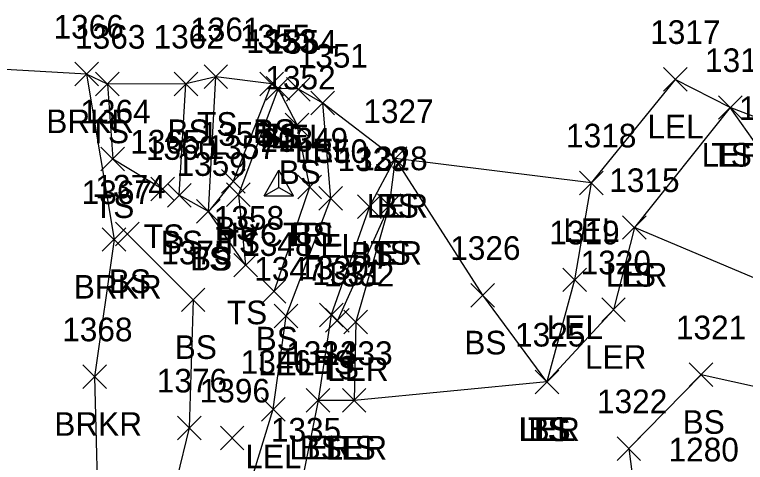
# Model space of a CAD drawing. Extents: x 1505684 to 1510253, y 730355 to 731397.
# Drawn here: x 1510141.5 to 1510203.3, y 730957.3 to 730995.2 of the extents above; entities that cross this region are included whole.
import ezdxf

# ---------------------------------------------------------------- set-up
doc = ezdxf.new("R2010")
doc.units = 0
for name, color, linetype in [('C_A', 7, 'Continuous'), ('C_I', 7, 'Continuous'), ('CPSM', 7, 'Continuous'), ('L_A', 7, 'Continuous'), ('L_I', 7, 'Continuous'), ('L_TIC', 7, 'Continuous'), ('LARO', 7, 'Continuous'), ('LAWE', 7, 'Continuous'), ('LELB', 7, 'Continuous'), ('LSOGP', 7, 'Continuous')]:
    doc.layers.add(name, color=color, linetype=linetype)

msp = doc.modelspace()

# ---------------------------------------------------------------- linework, layer by layer
at = {"layer": 'CPSM'}
for p, q in [((1510162.575, 730979.849), (1510163.825, 730982.014)), ((1510165.075, 730979.849), (1510163.825, 730982.014)), ((1510163.825, 730980.57), (1510163.825, 730982.014)), ((1510162.575, 730979.849), (1510163.825, 730980.57)), ((1510163.825, 730980.57), (1510163.825, 730980.57)), ((1510163.825, 730980.57), (1510165.075, 730979.849)), ((1510162.575, 730979.849), (1510165.075, 730979.849))]:
    msp.add_line(p, q, dxfattribs=at)
at = {"layer": 'L_TIC'}
for points in [[(1510146.562, 730989.156), (1510148.562, 730991.156)], [(1510148.562, 730989.156), (1510146.562, 730991.156)], [(1510157.499, 730988.933), (1510159.499, 730990.933)], [(1510159.499, 730988.933), (1510157.499, 730990.933)], [(1510148.331, 730988.302), (1510150.331, 730990.302)], [(1510150.331, 730988.302), (1510148.331, 730990.302)], [(1510154.968, 730988.315), (1510156.968, 730990.315)], [(1510156.968, 730988.315), (1510154.968, 730990.315)], [(1510162.22, 730988.325), (1510164.22, 730990.325)], [(1510164.22, 730988.325), (1510162.22, 730990.325)], [(1510196.37, 730988.705), (1510198.37, 730990.705)], [(1510198.37, 730988.705), (1510196.37, 730990.705)], [(1510162.768, 730987.944), (1510164.768, 730989.944)], [(1510164.768, 730987.944), (1510162.768, 730989.944)], [(1510162.768, 730987.944), (1510164.768, 730989.944)], [(1510164.768, 730987.944), (1510162.768, 730989.944)], [(1510164.484, 730987.873), (1510166.484, 730989.873)], [(1510166.484, 730987.873), (1510164.484, 730989.873)], [(1510166.547, 730986.697), (1510168.547, 730988.697)], [(1510168.547, 730986.697), (1510166.547, 730988.697)], [(1510201.014, 730986.326), (1510203.014, 730988.326)], [(1510203.014, 730986.326), (1510201.014, 730988.326)], [(1510201.014, 730986.326), (1510203.014, 730988.326)], [(1510203.014, 730986.326), (1510201.014, 730988.326)], [(1510164.377, 730984.851), (1510166.377, 730986.851)], [(1510166.377, 730984.851), (1510164.377, 730986.851)], [(1510172.671, 730982.007), (1510174.671, 730984.007)], [(1510174.671, 730982.007), (1510172.671, 730984.007)], [(1510172.671, 730982.007), (1510174.671, 730984.007)], [(1510174.671, 730982.007), (1510172.671, 730984.007)], [(1510148.777, 730981.976), (1510150.777, 730983.976)], [(1510150.777, 730981.976), (1510148.777, 730983.976)], [(1510158.968, 730980.086), (1510160.968, 730982.086)], [(1510160.968, 730980.086), (1510158.968, 730982.086)], [(1510165.448, 730979.599), (1510167.448, 730981.599)], [(1510167.448, 730979.599), (1510165.448, 730981.599)], [(1510189.257, 730979.947), (1510191.257, 730981.947)], [(1510191.257, 730979.947), (1510189.257, 730981.947)], [(1510152.993, 730979.431), (1510154.993, 730981.431)], [(1510154.993, 730979.431), (1510152.993, 730981.431)], [(1510159.407, 730978.959), (1510161.407, 730980.959)], [(1510161.407, 730978.959), (1510159.407, 730980.959)], [(1510154.401, 730978.897), (1510156.401, 730980.897)], [(1510156.401, 730978.897), (1510154.401, 730980.897)], [(1510167.214, 730978.63), (1510169.214, 730980.63)], [(1510169.214, 730978.63), (1510167.214, 730980.63)], [(1510170.486, 730977.94), (1510172.486, 730979.94)], [(1510172.486, 730977.94), (1510170.486, 730979.94)], [(1510172.163, 730978.018), (1510174.163, 730980.018)], [(1510174.163, 730978.018), (1510172.163, 730980.018)], [(1510172.163, 730978.018), (1510174.163, 730980.018)], [(1510174.163, 730978.018), (1510172.163, 730980.018)], [(1510156.871, 730977.538), (1510158.871, 730979.538)], [(1510158.871, 730977.538), (1510156.871, 730979.538)], [(1510156.871, 730977.538), (1510158.871, 730979.538)], [(1510158.871, 730977.538), (1510156.871, 730979.538)], [(1510192.91, 730976.171), (1510194.91, 730978.171)], [(1510194.91, 730976.171), (1510192.91, 730978.171)], [(1510192.91, 730976.171), (1510194.91, 730978.171)], [(1510194.91, 730976.171), (1510192.91, 730978.171)], [(1510150.004, 730975.626), (1510152.004, 730977.626)], [(1510152.004, 730975.626), (1510150.004, 730977.626)], [(1510148.891, 730975.157), (1510150.891, 730977.157)], [(1510150.891, 730975.157), (1510148.891, 730977.157)], [(1510160.018, 730972.985), (1510162.018, 730974.985)], [(1510162.018, 730972.985), (1510160.018, 730974.985)], [(1510187.848, 730971.742), (1510189.848, 730973.742)], [(1510189.848, 730971.742), (1510187.848, 730973.742)], [(1510162.425, 730970.767), (1510164.425, 730972.767)], [(1510164.425, 730970.767), (1510162.425, 730972.767)], [(1510180.076, 730970.432), (1510182.076, 730972.432)], [(1510182.076, 730970.432), (1510180.076, 730972.432)], [(1510155.58, 730970.051), (1510157.58, 730972.051)], [(1510157.58, 730970.051), (1510155.58, 730972.051)], [(1510191.142, 730969.212), (1510193.142, 730971.212)], [(1510193.142, 730969.212), (1510191.142, 730971.212)], [(1510163.438, 730968.672), (1510165.438, 730970.672)], [(1510165.438, 730968.672), (1510163.438, 730970.672)], [(1510167.262, 730968.776), (1510169.262, 730970.776)], [(1510169.262, 730968.776), (1510167.262, 730970.776)], [(1510167.782, 730968.304), (1510169.782, 730970.304)], [(1510169.782, 730968.304), (1510167.782, 730970.304)], [(1510169.338, 730968.187), (1510171.338, 730970.187)], [(1510171.338, 730968.187), (1510169.338, 730970.187)], [(1510147.239, 730963.543), (1510149.239, 730965.543)], [(1510149.239, 730963.543), (1510147.239, 730965.543)], [(1510198.546, 730963.713), (1510200.546, 730965.713)], [(1510200.546, 730963.713), (1510198.546, 730965.713)], [(1510185.509, 730963.098), (1510187.509, 730965.098)], [(1510187.509, 730963.098), (1510185.509, 730965.098)], [(1510185.509, 730963.098), (1510187.509, 730965.098)], [(1510187.509, 730963.098), (1510185.509, 730965.098)], [(1510185.509, 730963.098), (1510187.509, 730965.098)], [(1510187.509, 730963.098), (1510185.509, 730965.098)], [(1510185.509, 730963.098), (1510187.509, 730965.098)], [(1510187.509, 730963.098), (1510185.509, 730965.098)], [(1510166.147, 730961.543), (1510168.147, 730963.543)], [(1510168.147, 730961.543), (1510166.147, 730963.543)], [(1510166.147, 730961.543), (1510168.147, 730963.543)], [(1510168.147, 730961.543), (1510166.147, 730963.543)], [(1510169.201, 730961.539), (1510171.201, 730963.539)], [(1510171.201, 730961.539), (1510169.201, 730963.539)], [(1510169.201, 730961.539), (1510171.201, 730963.539)], [(1510171.201, 730961.539), (1510169.201, 730963.539)], [(1510162.353, 730960.789), (1510164.353, 730962.789)], [(1510164.353, 730960.789), (1510162.353, 730962.789)], [(1510155.251, 730959.212), (1510157.251, 730961.212)], [(1510157.251, 730959.212), (1510155.251, 730961.212)], [(1510158.881, 730958.364), (1510160.881, 730960.364)], [(1510160.881, 730958.364), (1510158.881, 730960.364)], [(1510192.439, 730957.459), (1510194.439, 730959.459)], [(1510194.439, 730957.459), (1510192.439, 730959.459)]]:
    msp.add_lwpolyline(points, dxfattribs=at)
at = {"layer": 'LARO'}
for points in [[(1510197.37, 730989.705), (1510190.257, 730980.947), (1510188.848, 730972.742), (1510186.509, 730964.098)], [(1510161.128, 730930.005), (1510158.373, 730935.357), (1510158.502, 730944.467), (1510160.297, 730951.834), (1510163.353, 730961.789), (1510164.438, 730969.672), (1510168.214, 730979.63), (1510167.547, 730987.697), (1510165.484, 730988.873)], [(1510202.014, 730987.326), (1510193.91, 730977.171), (1510192.142, 730970.212), (1510186.509, 730964.098)], [(1510173.671, 730983.007), (1510173.163, 730979.018), (1510170.338, 730969.187), (1510170.201, 730962.539), (1510167.147, 730962.543), (1510165.845, 730956.06), (1510163.044, 730951.454)]]:
    msp.add_lwpolyline(points, dxfattribs=at)
at = {"layer": 'LAWE'}
msp.add_lwpolyline([(1510147.562, 730990.156), (1510149.891, 730976.157), (1510148.239, 730964.543), (1510148.587, 730950.317), (1510150.043, 730940.021), (1510154.699, 730931.705), (1510151.716, 730923.73), (1510155.439, 730915.171), (1510157.525, 730908.642), (1510159.748, 730889.351), (1510165.212, 730879.843)], dxfattribs=at)
at = {"layer": 'LELB'}
for points in [[(1510163.768, 730988.944), (1510160.407, 730979.959), (1510161.018, 730973.985), (1510157.871, 730978.538), (1510158.499, 730989.933)], [(1510149.331, 730989.302), (1510149.777, 730982.976), (1510153.993, 730980.431)], [(1510163.425, 730971.767), (1510166.448, 730980.599), (1510165.377, 730985.851), (1510163.768, 730988.944), (1510163.22, 730989.325), (1510159.968, 730981.086), (1510157.871, 730978.538), (1510155.401, 730979.897), (1510155.968, 730989.315)], [(1510205.808, 730972.154), (1510204.891, 730983.266), (1510202.014, 730987.326)], [(1510211.127, 730983.825), (1510214.547, 730974.081), (1510212.454, 730970.755), (1510214.424, 730965.024), (1510219.359, 730956.811), (1510217.995, 730956.45), (1510207.598, 730962.932), (1510199.546, 730964.713), (1510193.439, 730958.459), (1510194.352, 730951.448), (1510175.146, 730950.785), (1510171.38, 730951.139)], [(1510186.509, 730964.098), (1510181.076, 730971.432), (1510173.671, 730983.007), (1510171.486, 730978.94), (1510168.262, 730969.776), (1510167.147, 730962.543)], [(1510173.163, 730979.018), (1510168.782, 730969.304)], [(1510151.004, 730976.626), (1510156.58, 730971.051), (1510156.251, 730960.212), (1510154.169, 730951.632), (1510155.837, 730946.251), (1510157.72, 730937.242), (1510159.355, 730928.387), (1510160.052, 730926.869), (1510160.762, 730916.086), (1510163.632, 730906.312), (1510169.271, 730896.105), (1510172.686, 730876.272)], [(1510212.454, 730970.755), (1510205.808, 730972.154), (1510193.91, 730977.171)], [(1510186.509, 730964.098), (1510170.201, 730962.539)]]:
    msp.add_lwpolyline(points, dxfattribs=at)
at = {"layer": 'LSOGP'}
msp.add_lwpolyline([(1510211.127, 730983.825), (1510202.014, 730987.326), (1510197.37, 730989.705), (1510190.257, 730980.947), (1510173.671, 730983.007), (1510167.547, 730987.697), (1510165.484, 730988.873), (1510163.768, 730988.944), (1510163.22, 730989.325), (1510158.499, 730989.933), (1510155.968, 730989.315), (1510149.331, 730989.302), (1510147.562, 730990.156), (1510122.024, 730991.611)], dxfattribs=at)

# ---------------------------------------------------------------- texts
at = {"layer": 'C_A'}
msp.add_text('HVCTRL', height=2, dxfattribs=at).set_placement((1510158.518, 730975.57))
at = {"layer": 'C_I'}
msp.add_text('20', height=2, dxfattribs=at).set_placement((1510162.274, 730983.57))
at = {"layer": 'L_A'}
for s, p in [('BRKR', (1510144.153, 730985.156)), ('TS', (1510156.909, 730984.933)), ('LEL', (1510195.008, 730984.705)), ('TS', (1510147.741, 730984.302)), ('BS', (1510154.409, 730984.315)), ('BS', (1510161.661, 730984.325)), ('TS', (1510162.178, 730983.944)), ('BS', (1510162.209, 730983.944)), ('LEL', (1510163.122, 730983.873)), ('LEL', (1510165.184, 730982.697)), ('LER', (1510199.597, 730982.326)), ('TS', (1510200.424, 730982.326)), ('BS', (1510163.818, 730980.851)), ('TS', (1510148.187, 730977.976)), ('LER', (1510171.254, 730978.007)), ('BS', (1510172.112, 730978.007)), ('BS', (1510158.409, 730976.086)), ('LEL', (1510187.894, 730975.947)), ('TS', (1510152.403, 730975.431)), ('BS', (1510164.888, 730975.599)), ('BS', (1510153.842, 730974.897)), ('TS', (1510158.817, 730974.959)), ('LEL', (1510165.852, 730974.63)), ('BS', (1510169.927, 730973.94)), ('LER', (1510170.746, 730974.018)), ('TS', (1510171.573, 730974.018)), ('TS', (1510156.281, 730973.538)), ('BS', (1510156.312, 730973.538)), ('LER', (1510191.493, 730972.171)), ('TS', (1510192.32, 730972.171)), ('BS', (1510149.445, 730971.626)), ('BRKR', (1510146.482, 730971.157)), ('TS', (1510159.427, 730968.985)), ('LEL', (1510186.486, 730967.742)), ('BS', (1510161.866, 730966.767)), ('BS', (1510155.021, 730966.051)), ('BS', (1510179.517, 730966.432)), ('BS', (1510166.702, 730964.776)), ('LER', (1510189.725, 730965.212)), ('LEL', (1510162.076, 730964.672)), ('TS', (1510167.192, 730964.304)), ('LER', (1510167.92, 730964.187)), ('BS', (1510197.987, 730959.713)), ('BRKR', (1510144.829, 730959.543)), ('TS', (1510184.919, 730959.098)), ('BS', (1510184.95, 730959.098)), ('LER', (1510184.092, 730959.098)), ('LEL', (1510184.147, 730959.098)), ('LER', (1510164.73, 730957.543)), ('BS', (1510165.588, 730957.543)), ('LER', (1510167.784, 730957.539)), ('TS', (1510168.61, 730957.539)), ('LEL', (1510160.991, 730956.789))]:
    msp.add_text(s, height=2, dxfattribs=at).set_placement(p)
at = {"layer": 'L_I'}
for s, p in [('1366', (1510144.767, 730993.156)), ('1361', (1510156.326, 730992.933)), ('1317', (1510195.244, 730992.705)), ('1363', (1510146.591, 730992.302)), ('1362', (1510153.228, 730992.315)), ('1355', (1510160.527, 730992.325)), ('1353', (1510161.075, 730991.944)), ('1353', (1510161.075, 730991.944)), ('1354', (1510162.792, 730991.873)), ('1351', (1510165.421, 730990.697)), ('1314', (1510199.888, 730990.326)), ('1314', (1510199.888, 730990.326)), ('1352', (1510162.684, 730988.851)), ('1364', (1510147.037, 730985.976)), ('1327', (1510170.979, 730986.007)), ('1327', (1510170.979, 730986.007)), ('1313', (1510202.765, 730986.266)), ('1356', (1510157.22, 730984.086)), ('1318', (1510188.131, 730983.947)), ('1365', (1510151.253, 730983.431)), ('1349', (1510163.747, 730983.599)), ('1360', (1510152.574, 730982.897)), ('1357', (1510157.714, 730982.959)), ('1350', (1510165.435, 730982.63)), ('1328', (1510170.47, 730982.018)), ('1328', (1510170.47, 730982.018)), ('1359', (1510155.17, 730981.538)), ('1359', (1510155.17, 730981.538)), ('1329', (1510168.786, 730981.94)), ('1315', (1510191.784, 730980.171)), ('1315', (1510191.784, 730980.171)), ('1374', (1510148.311, 730979.626)), ('1367', (1510147.151, 730979.157)), ('1358', (1510158.325, 730976.985)), ('1319', (1510186.714, 730975.742)), ('1348', (1510160.732, 730974.767)), ('1375', (1510153.887, 730974.051)), ('1326', (1510178.328, 730974.432)), ('1330', (1510165.482, 730972.776)), ('1320', (1510189.363, 730973.212)), ('1347', (1510161.746, 730972.672)), ('1331', (1510166.656, 730972.304)), ('1332', (1510167.645, 730972.187)), ('1368', (1510145.499, 730967.543)), ('1321', (1510197.42, 730967.713)), ('1325', (1510183.817, 730967.098)), ('1325', (1510183.817, 730967.098)), ('1325', (1510183.817, 730967.098)), ('1325', (1510183.817, 730967.098)), ('1334', (1510164.454, 730965.543)), ('1334', (1510164.454, 730965.543)), ('1333', (1510167.508, 730965.539)), ('1333', (1510167.508, 730965.539)), ('1346', (1510160.605, 730964.789)), ('1376', (1510153.503, 730963.212)), ('1396', (1510157.133, 730962.364)), ('1322', (1510190.746, 730961.459)), ('1335', (1510163.152, 730959.06)), ('1280', (1510196.799, 730957.377))]:
    msp.add_text(s, height=2, dxfattribs=at).set_placement(p)

doc.saveas('drawing.dxf')
